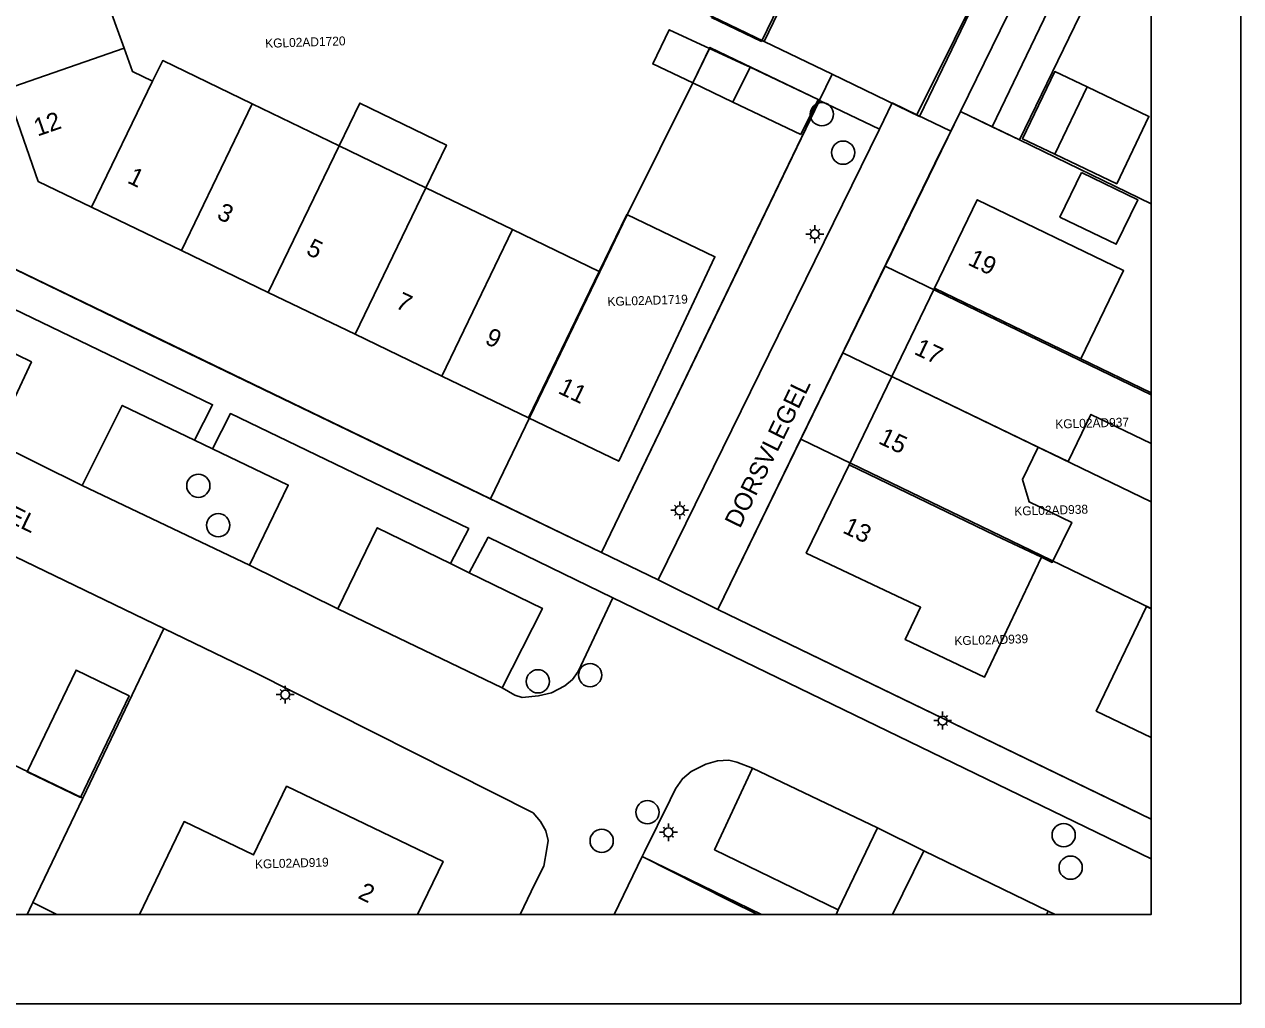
# Model space of a CAD drawing. Extents: x 124901 to 125496, y 515369 to 515789.
# Drawn here: x 125427.9 to 125495.9, y 515368.5 to 515423.4 of the extents above; entities that cross this region are included whole.
import ezdxf

# ---------------------------------------------------------------- set-up
doc = ezdxf.new("R2010")
doc.units = 0
for name, color, linetype in [('Alg Kaders', 7, 'Continuous'), ('Gebouw', 7, 'Continuous'), ('Lichtmast', 7, 'Continuous'), ('Luifel', 7, 'Continuous'), ('Onbegroeid terrein', 7, 'Continuous'), ('Parkeren', 7, 'Continuous'), ('Perceelnummers', 7, 'Continuous'), ('Perceelsgrenzen', 7, 'Continuous'), ('Putten', 7, 'Continuous'), ('Scheiding', 7, 'Continuous'), ('Teksten', 7, 'Continuous'), ('Vegetatie', 7, 'Continuous'), ('Voetpad', 7, 'Continuous'), ('Wegen lokale weg', 7, 'Continuous')]:
    doc.layers.add(name, color=color, linetype=linetype)

msp = doc.modelspace()

# ---------------------------------------------------------------- linework, layer by layer
at = {"layer": 'Alg Kaders'}
for points in [[(125495.925, 515789.043), (124901.425, 515789.043), (124901.425, 515368.543), (125495.925, 515368.543)], [(125490.925, 515784.043), (124906.425, 515784.043), (124906.425, 515373.543), (125490.925, 515373.543)]]:
    msp.add_lwpolyline(points, close=True, dxfattribs=at)
at = {"layer": 'Gebouw'}
for points in [[(125431.246, 515428.13), (125424.711, 515425.853), (125426.84, 515419.745), (125433.44, 515422.046)], [(125463.025, 515421.161), (125465.266, 515420.091), (125466.21, 515422.023), (125463.951, 515423.069)], [(125431.621, 515413.142), (125435.027, 515420.2), (125433.911, 515420.74), (125433.44, 515422.046), (125426.84, 515419.745), (125428.64, 515414.58)], [(125467.93, 515421.226), (125466.21, 515422.023), (125465.266, 515420.091), (125467.506, 515419.021), (125468.469, 515420.976)], [(125435.027, 515420.2), (125431.621, 515413.142), (125436.657, 515410.712), (125440.617, 515418.92), (125435.61, 515421.34)], [(125485.527, 515416.099), (125487.328, 515419.87), (125485.523, 515420.732), (125483.723, 515416.96)], [(125441.514, 515408.369), (125445.472, 515416.573), (125440.617, 515418.92), (125436.657, 515410.712)], [(125446.37, 515406.026), (125450.327, 515414.227), (125445.472, 515416.573), (125441.514, 515408.369)], [(125487.014, 515415.073), (125485.812, 515412.587), (125488.961, 515411.065), (125490.163, 515413.551)], [(125455.181, 515411.88), (125450.327, 515414.227), (125446.37, 515406.026), (125451.226, 515403.683)], [(125478.791, 515408.607), (125486.98, 515404.647), (125489.37, 515409.59), (125481.18, 515413.55)], [(125456.083, 515401.34), (125461.12, 515398.91), (125466.503, 515410.358), (125461.579, 515412.733), (125460.036, 515409.534)], [(125451.226, 515403.683), (125456.083, 515401.34), (125460.036, 515409.534), (125455.181, 515411.88)], [(125474.013, 515398.721), (125482.201, 515394.762), (125484.777, 515393.54), (125485.386, 515393.246), (125486.471, 515395.489), (125484.087, 515396.642), (125483.711, 515397.885), (125484.59, 515399.705), (125476.402, 515403.664)], [(125481.592, 515386.826), (125484.777, 515393.54), (125482.201, 515394.762), (125474.013, 515398.721), (125471.62, 515393.77), (125478.013, 515390.737), (125477.155, 515388.93)], [(125433.72, 515385.78), (125430.76, 515387.22), (125428.02, 515381.52), (125430.998, 515380.094)]]:
    msp.add_lwpolyline(points, close=True, dxfattribs=at)
for points in [[(125490.925, 515402.739), (125486.98, 515404.647), (125478.791, 515408.607), (125476.402, 515403.664), (125484.59, 515399.705), (125486.273, 515398.891), (125487.549, 515401.531), (125490.925, 515399.898)], [(125490.925, 515390.653), (125490.664, 515390.779), (125487.843, 515384.924), (125490.925, 515383.438)], [(125449.863, 515373.543), (125451.29, 515376.51), (125442.535, 515380.712), (125440.692, 515376.871), (125436.797, 515378.74), (125434.303, 515373.543)]]:
    msp.add_lwpolyline(points, dxfattribs=at)
at = {"layer": 'Lichtmast'}
for p, q in [((125471.796, 515411.629), (125471.596, 515411.628)), ((125471.884, 515411.84), (125471.814, 515411.911)), ((125472.096, 515411.928), (125472.096, 515412.128)), ((125472.308, 515411.84), (125472.379, 515411.912)), ((125472.396, 515411.628), (125472.596, 515411.628)), ((125471.884, 515411.416), (125471.812, 515411.345)), ((125472.096, 515411.328), (125472.096, 515411.128)), ((125472.308, 515411.416), (125472.378, 515411.345)), ((125464.533, 515396.465), (125464.533, 515396.665)), ((125464.233, 515396.166), (125464.033, 515396.165)), ((125464.321, 515395.953), (125464.249, 515395.882)), ((125464.321, 515396.377), (125464.251, 515396.448)), ((125464.745, 515396.377), (125464.816, 515396.449)), ((125464.745, 515395.953), (125464.815, 515395.882)), ((125464.833, 515396.165), (125465.033, 515396.165)), ((125464.533, 515395.865), (125464.533, 515395.665)), ((125442.16, 515385.847), (125441.96, 515385.846)), ((125442.248, 515386.058), (125442.178, 515386.129)), ((125442.46, 515386.146), (125442.46, 515386.346)), ((125442.672, 515386.058), (125442.743, 515386.13)), ((125442.76, 515385.846), (125442.96, 515385.846)), ((125442.248, 515385.634), (125442.176, 515385.563)), ((125442.46, 515385.546), (125442.46, 515385.346)), ((125442.672, 515385.634), (125442.742, 515385.563)), ((125478.946, 515384.396), (125478.746, 515384.395)), ((125479.034, 515384.607), (125478.964, 515384.678)), ((125479.246, 515384.695), (125479.246, 515384.895)), ((125479.458, 515384.607), (125479.529, 515384.679)), ((125479.546, 515384.395), (125479.746, 515384.395)), ((125479.034, 515384.183), (125478.962, 515384.112)), ((125479.246, 515384.095), (125479.246, 515383.895)), ((125479.458, 515384.183), (125479.528, 515384.112)), ((125463.693, 515378.352), (125463.623, 515378.423)), ((125463.905, 515378.44), (125463.905, 515378.64)), ((125464.117, 515378.352), (125464.188, 515378.424)), ((125463.605, 515378.141), (125463.405, 515378.14)), ((125463.693, 515377.928), (125463.621, 515377.857)), ((125463.905, 515377.84), (125463.905, 515377.64)), ((125464.117, 515377.928), (125464.187, 515377.857)), ((125464.205, 515378.14), (125464.405, 515378.14))]:
    msp.add_line(p, q, dxfattribs=at)
for centre in [(125472.096, 515411.628), (125464.533, 515396.165), (125442.46, 515385.846), (125479.246, 515384.395), (125463.905, 515378.14)]:
    msp.add_circle(centre, 0.25, dxfattribs=at)
at = {"layer": 'Luifel'}
for points in [[(125466.309, 515423.761), (125469.109, 515422.414), (125470.71, 515425.743), (125463.352, 515429.282), (125463.139, 515428.837), (125466.753, 515427.099), (125467.2, 515425.614)], [(125471.311, 515417.203), (125472.274, 515419.158), (125468.469, 515420.976), (125467.506, 515419.021)], [(125487.328, 515419.87), (125485.527, 515416.099), (125488.99, 515414.445), (125490.791, 515418.216)], [(125450.327, 515414.227), (125451.482, 515416.617), (125446.627, 515418.963), (125445.472, 515416.573)]]:
    msp.add_lwpolyline(points, close=True, dxfattribs=at)
at = {"layer": 'Onbegroeid terrein'}
for points in [[(125490.925, 515432.12), (125483.544, 515416.901), (125482.014, 515417.641), (125480.244, 515418.497), (125479.706, 515417.397), (125479.153, 515416.265), (125466.673, 515390.606), (125489.543, 515379.54), (125490.925, 515378.871)], [(125422.352, 515412.077), (125435.475, 515405.706), (125460.158, 515393.807), (125472.359, 515419.107), (125475.712, 515417.496), (125476.421, 515418.977), (125477.813, 515418.303), (125484.12, 515431.04)], [(125431.246, 515428.13), (125433.44, 515422.046), (125433.911, 515420.74), (125435.027, 515420.2), (125435.61, 515421.34), (125440.617, 515418.92), (125445.472, 515416.573), (125450.327, 515414.227), (125455.181, 515411.88), (125460.036, 515409.534), (125461.579, 515412.733), (125466.503, 515410.358), (125461.12, 515398.91), (125456.083, 515401.34), (125451.226, 515403.683), (125446.37, 515406.026), (125441.514, 515408.369), (125436.657, 515410.712), (125431.621, 515413.142), (125428.64, 515414.58), (125426.84, 515419.745)], [(125490.925, 515399.898), (125487.549, 515401.531), (125486.273, 515398.891), (125484.59, 515399.705), (125483.711, 515397.885), (125484.087, 515396.642), (125486.471, 515395.489), (125485.386, 515393.246), (125484.777, 515393.54), (125481.592, 515386.826), (125477.155, 515388.93), (125478.013, 515390.737), (125471.62, 515393.77), (125474.013, 515398.721), (125476.402, 515403.664), (125478.791, 515408.607), (125481.18, 515413.55), (125489.37, 515409.59), (125486.98, 515404.647), (125490.925, 515402.739)], [(125455.601, 515373.543), (125456.426, 515375.251), (125456.94, 515376.246), (125457.099, 515377.21), (125457.169, 515377.67), (125457.051, 515378.227), (125456.737, 515378.751), (125456.326, 515379.227), (125440.731, 515387.103), (125413.999, 515400.01), (125413.253, 515400.357), (125406.947, 515387.767), (125400.118, 515373.543)], [(125490.925, 515383.438), (125487.843, 515384.924), (125490.664, 515390.779), (125490.925, 515390.653)], [(125434.303, 515373.543), (125436.797, 515378.74), (125440.692, 515376.871), (125442.535, 515380.712), (125451.29, 515376.51), (125449.863, 515373.543)], [(125468.89, 515373.543), (125467.34, 515374.296), (125462.438, 515376.785), (125460.862, 515373.543)]]:
    msp.add_lwpolyline(points, dxfattribs=at)
for points in [[(125466.21, 515422.023), (125467.93, 515421.226), (125468.469, 515420.976), (125467.506, 515419.021), (125465.266, 515420.091), (125463.025, 515421.161), (125463.951, 515423.069)], [(125487.328, 515419.87), (125485.527, 515416.099), (125483.723, 515416.96), (125485.523, 515420.732)], [(125487.014, 515415.073), (125490.163, 515413.551), (125488.961, 515411.065), (125485.812, 515412.587)], [(125430.76, 515387.22), (125433.72, 515385.78), (125430.998, 515380.094), (125428.02, 515381.52)]]:
    msp.add_lwpolyline(points, close=True, dxfattribs=at)
at = {"layer": 'Parkeren'}
for points in [[(125426.147, 515400), (125428.263, 515404.477), (125424.088, 515406.504), (125423.096, 515406.986), (125419.029, 515408.959), (125416.917, 515404.45)], [(125440.458, 515393.088), (125442.629, 515397.577), (125438.387, 515399.612), (125437.38, 515400.095), (125433.34, 515402.034), (125431.103, 515397.551)], [(125447.607, 515395.185), (125445.408, 515390.647), (125454.607, 515386.226), (125456.851, 515390.676), (125452.759, 515392.672), (125451.71, 515393.183)], [(125473.4, 515373.789), (125475.61, 515378.394), (125468.603, 515381.726), (125466.483, 515377.164)]]:
    msp.add_lwpolyline(points, close=True, dxfattribs=at)
msp.add_lwpolyline([(125485.063, 515373.543), (125485.152, 515373.729), (125478.196, 515377.1), (125476.443, 515373.543)], dxfattribs=at)
at = {"layer": 'Perceelsgrenzen'}
for points in [[(125422.352, 515412.077), (125416.323, 515429.095), (125425.515, 515447.977), (125427.947, 515452.971), (125430.307, 515457.819), (125432.68, 515462.693), (125436.24, 515470.006), (125458.379, 515459.386), (125466.196, 515455.636), (125473.945, 515451.919), (125481.696, 515448.201), (125490.418, 515444.017), (125486.87, 515436.73), (125484.12, 515431.04), (125477.96, 515418.22), (125473.069, 515420.579), (125472.365, 515419.12), (125460.158, 515393.807), (125453.949, 515396.807)], [(125469.259, 515422.417), (125461.501, 515426.16), (125473.945, 515451.919), (125481.696, 515448.201)], [(125453.949, 515396.807), (125422.352, 515412.077), (125416.323, 515429.095), (125425.515, 515447.977), (125430.08, 515445.77), (125447.75, 515437.274), (125449.679, 515436.346), (125447.917, 515432.714), (125453.762, 515429.894), (125461.501, 515426.16), (125469.259, 515422.417), (125473.069, 515420.579), (125472.365, 515419.12), (125466.225, 515422.082), (125465.264, 515420.091), (125461.584, 515412.672), (125460.064, 515409.52)], [(125481.696, 515448.201), (125490.418, 515444.017), (125486.87, 515436.73), (125484.12, 515431.04), (125477.96, 515418.22), (125473.069, 515420.579), (125469.259, 515422.417)], [(125453.949, 515396.807), (125460.064, 515409.52), (125461.584, 515412.672), (125465.264, 515420.091), (125466.225, 515422.082), (125472.365, 515419.12), (125460.158, 515393.807)], [(125431.133, 515380.048), (125408.641, 515390.882), (125413.253, 515400.357), (125413.999, 515400.01), (125435.675, 515389.544)]]:
    msp.add_lwpolyline(points, close=True, dxfattribs=at)
for points in [[(125490.925, 515378.871), (125466.673, 515390.606), (125471.312, 515400.14), (125473.665, 515404.977), (125476.027, 515409.83), (125480.244, 515418.497), (125483.544, 515416.901), (125490.925, 515432.119)], [(125490.925, 515413.332), (125483.544, 515416.901), (125490.925, 515432.119)], [(125490.925, 515402.628), (125476.027, 515409.83), (125480.244, 515418.497), (125483.544, 515416.901), (125490.925, 515413.332)], [(125490.925, 515396.633), (125473.665, 515404.977), (125476.027, 515409.83), (125490.925, 515402.628)], [(125490.925, 515390.66), (125471.312, 515400.14), (125473.665, 515404.977), (125490.925, 515396.633)], [(125400.202, 515373.543), (125401.109, 515375.407), (125404.88, 515383.155), (125408.641, 515390.882), (125413.253, 515400.357), (125413.999, 515400.01), (125435.675, 515389.544), (125440.731, 515387.103), (125456.326, 515379.227), (125456.737, 515378.751), (125457.051, 515378.227), (125457.169, 515377.67), (125457.099, 515377.21), (125456.94, 515376.246), (125456.426, 515375.251), (125455.601, 515373.543)], [(125490.925, 515378.871), (125466.673, 515390.606), (125471.312, 515400.14), (125490.925, 515390.66)], [(125424.786, 515373.543), (125404.88, 515383.155), (125408.641, 515390.882), (125431.133, 515380.048), (125428.337, 515374.2), (125428.285, 515374.092), (125428.015, 515373.543)], [(125429.683, 515373.543), (125428.337, 515374.2), (125431.133, 515380.048), (125435.675, 515389.544), (125440.731, 515387.103), (125456.326, 515379.227), (125456.737, 515378.751), (125457.051, 515378.227), (125457.169, 515377.67), (125457.099, 515377.21), (125456.94, 515376.246), (125456.426, 515375.251), (125455.601, 515373.543)], [(125460.862, 515373.543), (125462.438, 515376.785), (125469.105, 515373.543)], [(125460.862, 515373.543), (125462.438, 515376.785), (125469.105, 515373.543)], [(125428.015, 515373.543), (125428.285, 515374.092), (125428.337, 515374.2), (125429.683, 515373.543)]]:
    msp.add_lwpolyline(points, dxfattribs=at)
at = {"layer": 'Putten'}
for centre in [(125472.49, 515418.34), (125473.68, 515416.19), (125437.6, 515397.54), (125438.71, 515395.33), (125456.6, 515386.59), (125459.52, 515386.94), (125462.73, 515379.26), (125460.17, 515377.66), (125486.02, 515377.98), (125486.41, 515376.16)]:
    msp.add_circle(centre, 0.65, dxfattribs=at)
at = {"layer": 'Scheiding'}
msp.add_line((125467.34, 515374.296), (125468.89, 515373.543), dxfattribs=at)
at = {"layer": 'Vegetatie'}
for points in [[(125490.925, 515440.255), (125486.902, 515432.118), (125480.244, 515418.497), (125482.014, 515417.641), (125490.925, 515436.143)], [(125490.925, 515436.143), (125482.014, 515417.641), (125483.544, 515416.901), (125490.925, 515432.12)], [(125473.298, 515373.543), (125473.4, 515373.789), (125466.483, 515377.164), (125468.603, 515381.726), (125467.733, 515382.057), (125467.28, 515382.177), (125466.652, 515382.148), (125466.004, 515381.953), (125465.168, 515381.544), (125464.684, 515381.133), (125464.3, 515380.578), (125464.005, 515379.951), (125462.561, 515377.038), (125462.438, 515376.785), (125467.34, 515374.296), (125468.89, 515373.543)], [(125476.443, 515373.543), (125478.196, 515377.1), (125475.61, 515378.394), (125473.4, 515373.789), (125473.298, 515373.543)], [(125485.538, 515373.543), (125485.152, 515373.729), (125485.063, 515373.543)]]:
    msp.add_lwpolyline(points, dxfattribs=at)
for points in [[(125463.328, 515392.279), (125475.712, 515417.496), (125472.359, 515419.107), (125460.158, 515393.807)], [(125428.263, 515404.477), (125426.147, 515400), (125431.103, 515397.551), (125433.34, 515402.034), (125437.38, 515400.095), (125438.393, 515402.078), (125425.11, 515408.481), (125424.088, 515406.504)], [(125445.408, 515390.647), (125447.607, 515395.185), (125451.71, 515393.183), (125452.728, 515395.141), (125439.394, 515401.581), (125438.387, 515399.612), (125442.629, 515397.577), (125440.458, 515393.088)], [(125454.607, 515386.226), (125455.315, 515385.823), (125455.726, 515385.684), (125456.625, 515385.781), (125457.353, 515385.944), (125458.112, 515386.345), (125458.529, 515386.685), (125458.85, 515387.143), (125460.797, 515391.27), (125453.821, 515394.656), (125452.759, 515392.672), (125456.851, 515390.676)]]:
    msp.add_lwpolyline(points, close=True, dxfattribs=at)
at = {"layer": 'Voetpad'}
for points in [[(125490.925, 515443.767), (125490.552, 515443.952), (125486.87, 515436.73), (125484.12, 515431.04), (125477.813, 515418.303), (125479.706, 515417.397), (125480.244, 515418.497), (125486.902, 515432.118), (125490.925, 515440.255)], [(125490.925, 515378.871), (125489.543, 515379.54), (125466.673, 515390.606), (125463.328, 515392.279), (125460.158, 515393.807), (125435.475, 515405.706), (125422.352, 515412.077), (125420.891, 515416.201), (125419.603, 515413.638), (125420.617, 515410.742), (125424.199, 515408.973), (125423.096, 515406.986), (125424.088, 515406.504), (125425.11, 515408.481), (125438.393, 515402.078), (125437.38, 515400.095), (125438.387, 515399.612), (125439.394, 515401.581), (125452.728, 515395.141), (125451.71, 515393.183), (125452.759, 515392.672), (125453.821, 515394.656), (125460.797, 515391.27), (125490.925, 515376.662)]]:
    msp.add_lwpolyline(points, dxfattribs=at)
msp.add_lwpolyline([(125477.813, 515418.303), (125476.421, 515418.977), (125475.712, 515417.496), (125463.328, 515392.279), (125466.673, 515390.606), (125479.153, 515416.265), (125479.706, 515417.397)], close=True, dxfattribs=at)
at = {"layer": 'Wegen lokale weg'}
for points in [[(125413.999, 515400.01), (125440.731, 515387.103), (125456.326, 515379.227), (125456.737, 515378.751), (125457.051, 515378.227), (125457.169, 515377.67), (125457.099, 515377.21), (125456.94, 515376.246), (125456.426, 515375.251), (125455.601, 515373.543)], [(125490.925, 515376.662), (125460.797, 515391.27), (125458.85, 515387.143), (125458.529, 515386.685), (125458.112, 515386.345), (125457.353, 515385.944), (125456.625, 515385.781), (125455.726, 515385.684), (125455.315, 515385.823), (125454.607, 515386.226), (125445.408, 515390.647), (125440.458, 515393.088), (125431.103, 515397.551), (125426.147, 515400)], [(125460.862, 515373.543), (125462.438, 515376.785), (125462.561, 515377.038), (125464.005, 515379.951), (125464.3, 515380.578), (125464.684, 515381.133), (125465.168, 515381.544), (125466.004, 515381.953), (125466.652, 515382.148), (125467.28, 515382.177), (125467.733, 515382.057), (125468.603, 515381.726), (125475.61, 515378.394), (125478.196, 515377.1), (125485.152, 515373.729), (125485.538, 515373.543)]]:
    msp.add_lwpolyline(points, dxfattribs=at)

# ---------------------------------------------------------------- texts
at = {"layer": 'Perceelnummers'}
for s, rotation, p in [('KGL02AD1720', 1.8332, (125441.347, 515422.057)), ('KGL02AD1719', 1.83342, (125460.5, 515407.599)), ('KGL02AD937', 1.63553, (125485.559, 515400.742)), ('KGL02AD938', 1.63551, (125483.266, 515395.865)), ('KGL02AD939', 1.63547, (125479.913, 515388.61)), ('KGL02AD919', 1.63501, (125440.776, 515376.105))]:
    msp.add_text(s, height=0.5, rotation=rotation, dxfattribs=at).set_placement(p)
at = {"layer": 'Teksten'}
for s, rotation, p in [('12', 19.2, (125428.604, 515417.087)), ('1', 334.2, (125433.573, 515414.528)), ('3', 334.2, (125438.573, 515412.528)), ('5', 334.2, (125443.573, 515410.528)), ('19', 334.2, (125480.599, 515409.939)), ('7', 334.2, (125448.573, 515407.528)), ('9', 334.2, (125453.573, 515405.528)), ('17', 334.2, (125477.599, 515404.939)), ('11', 334.2, (125457.676, 515402.746)), ('DORSVLEGEL', 63.9, (125467.903, 515395.109)), ('15', 334.2, (125475.599, 515399.939)), ('DORSVLEGEL', 334.2, (125420.099, 515398.819)), ('13', 334.6, (125473.6, 515394.932)), ('2', 334.3, (125446.472, 515374.476))]:
    msp.add_text(s, height=1, rotation=rotation, dxfattribs=at).set_placement(p)

doc.saveas('drawing.dxf')
